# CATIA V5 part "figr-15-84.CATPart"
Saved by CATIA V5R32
Part number: Part1
Bounding box of the stored display mesh (mm): x 0 to 27, y -46 to 46, z -30 to 30
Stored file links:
  D:\PROJECTS\Project 2022\CATIA V5 6R 2022\Resources\Part Files\c15_catia_v5_6r2022_prt\figr-15-84.CATPart
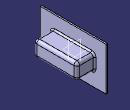
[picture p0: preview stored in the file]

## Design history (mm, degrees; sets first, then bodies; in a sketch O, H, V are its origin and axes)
SheetMetalParameters1: Thickness 2, BendRadius 4, KFactor 0.400515 {= log(min(100,max(20*SheetMetalParameters1.BendRadius,SheetMetalParameters1.Thickness)/SheetMetalParameters1.Thickness))/log(100)/2}, ReliefRadialLength 1, ReliefAxialLength 2, MinimumBendRadius 0
Body1 (main body)
  Sketch1 on yz-plane, origin (0, 0, 0), H (0, 1, 0), V (0, 0, 1)
    line L1 (46, 30) -> (46, -30)
    line L2 (46, -30) -> (-46, -30)
    line L3 (-46, -30) -> (-46, 30)
    line L4 (-46, 30) -> (46, 30)
    vertical: L1 V, L3 V
    horizontal: L2 H, L4 H
    equidistance: L1 L3 O, L2 L4 O
  Wall1: Thickness 2, Profile Sketch1, OffsetValue 0
  Sketch2 on face of Wall1, origin (2, 0, 0), H (0, 1, 0), V (0, 0, 1)
    line L1 (28, 9) -> (28, -9)
    line L2 (28, -9) -> (-28, -9)
    line L3 (-28, -9) -> (-28, 9)
    line L4 (-28, 9) -> (28, 9)
    vertical: L1 V, L3 V
    horizontal: L2 H, L4 H
    equidistance: L1 L3 O, L2 L4 O
  d_Stamp1: NewRoot_AttribNormalisation "No Standard", Stamp_FilletRadius 2, Stamp_IntersectFilletRadius 2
